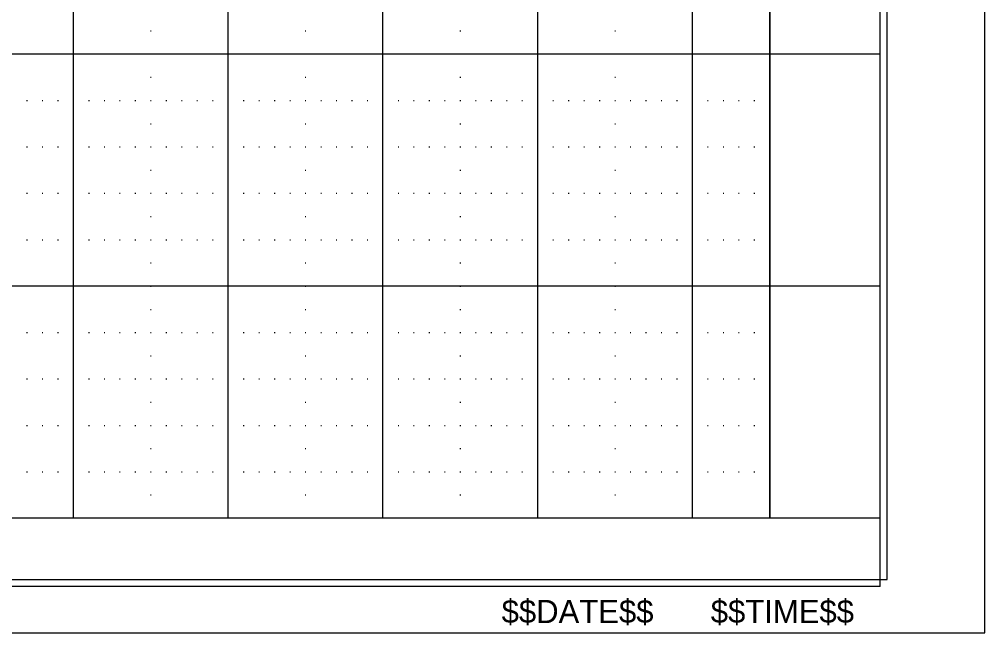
# Model space of a CAD drawing. Extents: x -1.3 to 32, y -0.2 to 20.7.
# Drawn here: x 27.879 to 32.038, y -0.229 to 2.414 of the extents above; entities that cross this region are included whole.
import ezdxf

# ---------------------------------------------------------------- set-up
doc = ezdxf.new("R2010")
doc.units = 0
for name, color, linetype in [('Level 1', 7, 'Continuous'), ('Level 37', 7, 'Continuous'), ('Level 4', 7, 'Continuous'), ('Level 48', 7, 'Continuous'), ('Level 5', 7, 'Continuous'), ('Level 62', 7, 'Continuous'), ('Level 63', 7, 'Continuous')]:
    doc.layers.add(name, color=color, linetype=linetype)

msp = doc.modelspace()

# ---------------------------------------------------------------- linework, layer by layer
at = {"layer": 'Level 1'}
for q in [(31.588, 20.516), (-0.03, -0.03)]:
    msp.add_line((31.588, -0.03), q, dxfattribs=at)
at = {"layer": 'Level 37'}
for p, q in [((31.1123, 10.264), (31.1123, 0.264)), ((31.1123, 0.264), (0.7787, 0.2635))]:
    msp.add_line(p, q, dxfattribs=at)
at = {"layer": 'Level 4'}
for p, q in [((28.1123, 0.264), (28.1123, 10.264)), ((28.779, 0.264), (28.779, 10.264)), ((29.4457, 0.264), (29.4457, 10.264)), ((30.1123, 0.264), (30.1123, 10.264)), ((30.779, 0.264), (30.779, 10.264)), ((31.1123, 0.264), (31.1123, 10.264)), ((31.588, 2.264), (-0.03, 2.264)), ((31.588, 1.264), (-0.03, 1.264)), ((31.588, 0.264), (0.4456, 0.264))]:
    msp.add_line(p, q, dxfattribs=at)
at = {"layer": 'Level 5'}
for p, q in [((28.444, 2.364), (28.4473, 2.364)), ((29.1107, 2.364), (29.114, 2.364)), ((29.7773, 2.364), (29.7807, 2.364)), ((30.444, 2.364), (30.4473, 2.364)), ((28.444, 2.164), (28.4473, 2.164)), ((29.1107, 2.164), (29.114, 2.164)), ((29.7773, 2.164), (29.7807, 2.164)), ((30.444, 2.164), (30.4473, 2.164)), ((27.9107, 2.064), (27.914, 2.064)), ((27.9773, 2.064), (27.9807, 2.064)), ((28.044, 2.064), (28.0473, 2.064)), ((28.1773, 2.064), (28.1807, 2.064)), ((28.244, 2.064), (28.2473, 2.064)), ((28.3107, 2.064), (28.314, 2.064)), ((28.3773, 2.064), (28.3807, 2.064)), ((28.444, 2.064), (28.4473, 2.064)), ((28.5107, 2.064), (28.514, 2.064)), ((28.5773, 2.064), (28.5807, 2.064)), ((28.644, 2.064), (28.6473, 2.064)), ((28.7107, 2.064), (28.714, 2.064)), ((28.844, 2.064), (28.8473, 2.064)), ((28.9107, 2.064), (28.914, 2.064)), ((28.9773, 2.064), (28.9807, 2.064)), ((29.044, 2.064), (29.0473, 2.064)), ((29.1107, 2.064), (29.114, 2.064)), ((29.1773, 2.064), (29.1807, 2.064)), ((29.244, 2.064), (29.2473, 2.064)), ((29.3107, 2.064), (29.314, 2.064)), ((29.3773, 2.064), (29.3807, 2.064)), ((29.5107, 2.064), (29.514, 2.064)), ((29.5773, 2.064), (29.5807, 2.064)), ((29.644, 2.064), (29.6473, 2.064)), ((29.7107, 2.064), (29.714, 2.064)), ((29.7773, 2.064), (29.7807, 2.064)), ((29.844, 2.064), (29.8473, 2.064)), ((29.9107, 2.064), (29.914, 2.064)), ((29.9773, 2.064), (29.9807, 2.064)), ((30.044, 2.064), (30.0473, 2.064)), ((30.1773, 2.064), (30.1807, 2.064)), ((30.244, 2.064), (30.2473, 2.064)), ((30.3107, 2.064), (30.314, 2.064)), ((30.3773, 2.064), (30.3807, 2.064)), ((30.444, 2.064), (30.4473, 2.064)), ((30.5107, 2.064), (30.514, 2.064)), ((30.5773, 2.064), (30.5807, 2.064)), ((30.644, 2.064), (30.6473, 2.064)), ((30.7107, 2.064), (30.714, 2.064)), ((30.844, 2.064), (30.8473, 2.064)), ((30.9107, 2.064), (30.914, 2.064)), ((30.9773, 2.064), (30.9807, 2.064)), ((31.044, 2.064), (31.0473, 2.064)), ((28.444, 1.964), (28.4473, 1.964)), ((29.1107, 1.964), (29.114, 1.964)), ((29.7773, 1.964), (29.7807, 1.964)), ((30.444, 1.964), (30.4473, 1.964)), ((27.9107, 1.864), (27.914, 1.864)), ((27.9773, 1.864), (27.9807, 1.864)), ((28.044, 1.864), (28.0473, 1.864)), ((28.1773, 1.864), (28.1807, 1.864)), ((28.244, 1.864), (28.2473, 1.864)), ((28.3107, 1.864), (28.314, 1.864)), ((28.3773, 1.864), (28.3807, 1.864)), ((28.444, 1.864), (28.4473, 1.864)), ((28.5107, 1.864), (28.514, 1.864)), ((28.5773, 1.864), (28.5807, 1.864)), ((28.644, 1.864), (28.6473, 1.864)), ((28.7107, 1.864), (28.714, 1.864)), ((28.844, 1.864), (28.8473, 1.864)), ((28.9107, 1.864), (28.914, 1.864)), ((28.9773, 1.864), (28.9807, 1.864)), ((29.044, 1.864), (29.0473, 1.864)), ((29.1107, 1.864), (29.114, 1.864)), ((29.1773, 1.864), (29.1807, 1.864)), ((29.244, 1.864), (29.2473, 1.864)), ((29.3107, 1.864), (29.314, 1.864)), ((29.3773, 1.864), (29.3807, 1.864)), ((29.5107, 1.864), (29.514, 1.864)), ((29.5773, 1.864), (29.5807, 1.864)), ((29.644, 1.864), (29.6473, 1.864)), ((29.7107, 1.864), (29.714, 1.864)), ((29.7773, 1.864), (29.7807, 1.864)), ((29.844, 1.864), (29.8473, 1.864)), ((29.9107, 1.864), (29.914, 1.864)), ((29.9773, 1.864), (29.9807, 1.864)), ((30.044, 1.864), (30.0473, 1.864)), ((30.1773, 1.864), (30.1807, 1.864)), ((30.244, 1.864), (30.2473, 1.864)), ((30.3107, 1.864), (30.314, 1.864)), ((30.3773, 1.864), (30.3807, 1.864)), ((30.444, 1.864), (30.4473, 1.864)), ((30.5107, 1.864), (30.514, 1.864)), ((30.5773, 1.864), (30.5807, 1.864)), ((30.644, 1.864), (30.6473, 1.864)), ((30.7107, 1.864), (30.714, 1.864)), ((30.844, 1.864), (30.8473, 1.864)), ((30.9107, 1.864), (30.914, 1.864)), ((30.9773, 1.864), (30.9807, 1.864)), ((31.044, 1.864), (31.0473, 1.864)), ((28.444, 1.764), (28.4473, 1.764)), ((29.1107, 1.764), (29.114, 1.764)), ((29.7773, 1.764), (29.7807, 1.764)), ((30.444, 1.764), (30.4473, 1.764)), ((27.9107, 1.664), (27.914, 1.664)), ((27.9773, 1.664), (27.9807, 1.664)), ((28.044, 1.664), (28.0473, 1.664)), ((28.1773, 1.664), (28.1807, 1.664)), ((28.244, 1.664), (28.2473, 1.664)), ((28.3107, 1.664), (28.314, 1.664)), ((28.3773, 1.664), (28.3807, 1.664)), ((28.444, 1.664), (28.4473, 1.664)), ((28.5107, 1.664), (28.514, 1.664)), ((28.5773, 1.664), (28.5807, 1.664)), ((28.644, 1.664), (28.6473, 1.664)), ((28.7107, 1.664), (28.714, 1.664)), ((28.844, 1.664), (28.8473, 1.664)), ((28.9107, 1.664), (28.914, 1.664)), ((28.9773, 1.664), (28.9807, 1.664)), ((29.044, 1.664), (29.0473, 1.664)), ((29.1107, 1.664), (29.114, 1.664)), ((29.1773, 1.664), (29.1807, 1.664)), ((29.244, 1.664), (29.2473, 1.664)), ((29.3107, 1.664), (29.314, 1.664)), ((29.3773, 1.664), (29.3807, 1.664)), ((29.5107, 1.664), (29.514, 1.664)), ((29.5773, 1.664), (29.5807, 1.664)), ((29.644, 1.664), (29.6473, 1.664)), ((29.7107, 1.664), (29.714, 1.664)), ((29.7773, 1.664), (29.7807, 1.664)), ((29.844, 1.664), (29.8473, 1.664)), ((29.9107, 1.664), (29.914, 1.664)), ((29.9773, 1.664), (29.9807, 1.664)), ((30.044, 1.664), (30.0473, 1.664)), ((30.1773, 1.664), (30.1807, 1.664)), ((30.244, 1.664), (30.2473, 1.664)), ((30.3107, 1.664), (30.314, 1.664)), ((30.3773, 1.664), (30.3807, 1.664)), ((30.444, 1.664), (30.4473, 1.664)), ((30.5107, 1.664), (30.514, 1.664)), ((30.5773, 1.664), (30.5807, 1.664)), ((30.644, 1.664), (30.6473, 1.664)), ((30.7107, 1.664), (30.714, 1.664)), ((30.844, 1.664), (30.8473, 1.664)), ((30.9107, 1.664), (30.914, 1.664)), ((30.9773, 1.664), (30.9807, 1.664)), ((31.044, 1.664), (31.0473, 1.664)), ((28.444, 1.564), (28.4473, 1.564)), ((29.1107, 1.564), (29.114, 1.564)), ((29.7773, 1.564), (29.7807, 1.564)), ((30.444, 1.564), (30.4473, 1.564)), ((27.9107, 1.464), (27.914, 1.464)), ((27.9773, 1.464), (27.9807, 1.464)), ((28.044, 1.464), (28.0473, 1.464)), ((28.1773, 1.464), (28.1807, 1.464)), ((28.244, 1.464), (28.2473, 1.464)), ((28.3107, 1.464), (28.314, 1.464)), ((28.3773, 1.464), (28.3807, 1.464)), ((28.444, 1.464), (28.4473, 1.464)), ((28.5107, 1.464), (28.514, 1.464)), ((28.5773, 1.464), (28.5807, 1.464)), ((28.644, 1.464), (28.6473, 1.464)), ((28.7107, 1.464), (28.714, 1.464)), ((28.844, 1.464), (28.8473, 1.464)), ((28.9107, 1.464), (28.914, 1.464)), ((28.9773, 1.464), (28.9807, 1.464)), ((29.044, 1.464), (29.0473, 1.464)), ((29.1107, 1.464), (29.114, 1.464)), ((29.1773, 1.464), (29.1807, 1.464)), ((29.244, 1.464), (29.2473, 1.464)), ((29.3107, 1.464), (29.314, 1.464)), ((29.3773, 1.464), (29.3807, 1.464)), ((29.5107, 1.464), (29.514, 1.464)), ((29.5773, 1.464), (29.5807, 1.464)), ((29.644, 1.464), (29.6473, 1.464)), ((29.7107, 1.464), (29.714, 1.464)), ((29.7773, 1.464), (29.7807, 1.464)), ((29.844, 1.464), (29.8473, 1.464)), ((29.9107, 1.464), (29.914, 1.464)), ((29.9773, 1.464), (29.9807, 1.464)), ((30.044, 1.464), (30.0473, 1.464)), ((30.1773, 1.464), (30.1807, 1.464)), ((30.244, 1.464), (30.2473, 1.464)), ((30.3107, 1.464), (30.314, 1.464)), ((30.3773, 1.464), (30.3807, 1.464)), ((30.444, 1.464), (30.4473, 1.464)), ((30.5107, 1.464), (30.514, 1.464)), ((30.5773, 1.464), (30.5807, 1.464)), ((30.644, 1.464), (30.6473, 1.464)), ((30.7107, 1.464), (30.714, 1.464)), ((30.844, 1.464), (30.8473, 1.464)), ((30.9107, 1.464), (30.914, 1.464)), ((30.9773, 1.464), (30.9807, 1.464)), ((31.044, 1.464), (31.0473, 1.464)), ((28.444, 1.364), (28.4473, 1.364)), ((29.1107, 1.364), (29.114, 1.364)), ((29.7773, 1.364), (29.7807, 1.364)), ((30.444, 1.364), (30.4473, 1.364)), ((28.444, 1.264), (28.4473, 1.264)), ((29.1107, 1.264), (29.114, 1.264)), ((29.7773, 1.264), (29.7807, 1.264)), ((30.444, 1.264), (30.4473, 1.264)), ((28.444, 1.164), (28.4473, 1.164)), ((29.1107, 1.164), (29.114, 1.164)), ((29.7773, 1.164), (29.7807, 1.164)), ((30.444, 1.164), (30.4473, 1.164)), ((27.9107, 1.064), (27.914, 1.064)), ((27.9773, 1.064), (27.9807, 1.064)), ((28.044, 1.064), (28.0473, 1.064)), ((28.1773, 1.064), (28.1807, 1.064)), ((28.244, 1.064), (28.2473, 1.064)), ((28.3107, 1.064), (28.314, 1.064)), ((28.3773, 1.064), (28.3807, 1.064)), ((28.444, 1.064), (28.4473, 1.064)), ((28.5107, 1.064), (28.514, 1.064)), ((28.5773, 1.064), (28.5807, 1.064)), ((28.644, 1.064), (28.6473, 1.064)), ((28.7107, 1.064), (28.714, 1.064)), ((28.844, 1.064), (28.8473, 1.064)), ((28.9107, 1.064), (28.914, 1.064)), ((28.9773, 1.064), (28.9807, 1.064)), ((29.044, 1.064), (29.0473, 1.064)), ((29.1107, 1.064), (29.114, 1.064)), ((29.1773, 1.064), (29.1807, 1.064)), ((29.244, 1.064), (29.2473, 1.064)), ((29.3107, 1.064), (29.314, 1.064)), ((29.3773, 1.064), (29.3807, 1.064)), ((29.5107, 1.064), (29.514, 1.064)), ((29.5773, 1.064), (29.5807, 1.064)), ((29.644, 1.064), (29.6473, 1.064)), ((29.7107, 1.064), (29.714, 1.064)), ((29.7773, 1.064), (29.7807, 1.064)), ((29.844, 1.064), (29.8473, 1.064)), ((29.9107, 1.064), (29.914, 1.064)), ((29.9773, 1.064), (29.9807, 1.064)), ((30.044, 1.064), (30.0473, 1.064)), ((30.1773, 1.064), (30.1807, 1.064)), ((30.244, 1.064), (30.2473, 1.064)), ((30.3107, 1.064), (30.314, 1.064)), ((30.3773, 1.064), (30.3807, 1.064)), ((30.444, 1.064), (30.4473, 1.064)), ((30.5107, 1.064), (30.514, 1.064)), ((30.5773, 1.064), (30.5807, 1.064)), ((30.644, 1.064), (30.6473, 1.064)), ((30.7107, 1.064), (30.714, 1.064)), ((30.844, 1.064), (30.8473, 1.064)), ((30.9107, 1.064), (30.914, 1.064)), ((30.9773, 1.064), (30.9807, 1.064)), ((31.044, 1.064), (31.0473, 1.064)), ((28.444, 0.964), (28.4473, 0.964)), ((29.1107, 0.964), (29.114, 0.964)), ((29.7773, 0.964), (29.7807, 0.964)), ((30.444, 0.964), (30.4473, 0.964)), ((27.9107, 0.864), (27.914, 0.864)), ((27.9773, 0.864), (27.9807, 0.864)), ((28.044, 0.864), (28.0473, 0.864)), ((28.1773, 0.864), (28.1807, 0.864)), ((28.244, 0.864), (28.2473, 0.864)), ((28.3107, 0.864), (28.314, 0.864)), ((28.3773, 0.864), (28.3807, 0.864)), ((28.444, 0.864), (28.4473, 0.864)), ((28.5107, 0.864), (28.514, 0.864)), ((28.5773, 0.864), (28.5807, 0.864)), ((28.644, 0.864), (28.6473, 0.864)), ((28.7107, 0.864), (28.714, 0.864)), ((28.844, 0.864), (28.8473, 0.864)), ((28.9107, 0.864), (28.914, 0.864)), ((28.9773, 0.864), (28.9807, 0.864)), ((29.044, 0.864), (29.0473, 0.864)), ((29.1107, 0.864), (29.114, 0.864)), ((29.1773, 0.864), (29.1807, 0.864)), ((29.244, 0.864), (29.2473, 0.864)), ((29.3107, 0.864), (29.314, 0.864)), ((29.3773, 0.864), (29.3807, 0.864)), ((29.5107, 0.864), (29.514, 0.864)), ((29.5773, 0.864), (29.5807, 0.864)), ((29.644, 0.864), (29.6473, 0.864)), ((29.7107, 0.864), (29.714, 0.864)), ((29.7773, 0.864), (29.7807, 0.864)), ((29.844, 0.864), (29.8473, 0.864)), ((29.9107, 0.864), (29.914, 0.864)), ((29.9773, 0.864), (29.9807, 0.864)), ((30.044, 0.864), (30.0473, 0.864)), ((30.1773, 0.864), (30.1807, 0.864)), ((30.244, 0.864), (30.2473, 0.864)), ((30.3107, 0.864), (30.314, 0.864)), ((30.3773, 0.864), (30.3807, 0.864)), ((30.444, 0.864), (30.4473, 0.864)), ((30.5107, 0.864), (30.514, 0.864)), ((30.5773, 0.864), (30.5807, 0.864)), ((30.644, 0.864), (30.6473, 0.864)), ((30.7107, 0.864), (30.714, 0.864)), ((30.844, 0.864), (30.8473, 0.864)), ((30.9107, 0.864), (30.914, 0.864)), ((30.9773, 0.864), (30.9807, 0.864)), ((31.044, 0.864), (31.0473, 0.864)), ((28.444, 0.764), (28.4473, 0.764)), ((29.1107, 0.764), (29.114, 0.764)), ((29.7773, 0.764), (29.7807, 0.764)), ((30.444, 0.764), (30.4473, 0.764)), ((27.9107, 0.664), (27.914, 0.664)), ((27.9773, 0.664), (27.9807, 0.664)), ((28.044, 0.664), (28.0473, 0.664)), ((28.1773, 0.664), (28.1807, 0.664)), ((28.244, 0.664), (28.2473, 0.664)), ((28.3107, 0.664), (28.314, 0.664)), ((28.3773, 0.664), (28.3807, 0.664)), ((28.444, 0.664), (28.4473, 0.664)), ((28.5107, 0.664), (28.514, 0.664)), ((28.5773, 0.664), (28.5807, 0.664)), ((28.644, 0.664), (28.6473, 0.664)), ((28.7107, 0.664), (28.714, 0.664)), ((28.844, 0.664), (28.8473, 0.664)), ((28.9107, 0.664), (28.914, 0.664)), ((28.9773, 0.664), (28.9807, 0.664)), ((29.044, 0.664), (29.0473, 0.664)), ((29.1107, 0.664), (29.114, 0.664)), ((29.1773, 0.664), (29.1807, 0.664)), ((29.244, 0.664), (29.2473, 0.664)), ((29.3107, 0.664), (29.314, 0.664)), ((29.3773, 0.664), (29.3807, 0.664)), ((29.5107, 0.664), (29.514, 0.664)), ((29.5773, 0.664), (29.5807, 0.664)), ((29.644, 0.664), (29.6473, 0.664)), ((29.7107, 0.664), (29.714, 0.664)), ((29.7773, 0.664), (29.7807, 0.664)), ((29.844, 0.664), (29.8473, 0.664)), ((29.9107, 0.664), (29.914, 0.664)), ((29.9773, 0.664), (29.9807, 0.664)), ((30.044, 0.664), (30.0473, 0.664)), ((30.1773, 0.664), (30.1807, 0.664)), ((30.244, 0.664), (30.2473, 0.664)), ((30.3107, 0.664), (30.314, 0.664)), ((30.3773, 0.664), (30.3807, 0.664)), ((30.444, 0.664), (30.4473, 0.664)), ((30.5107, 0.664), (30.514, 0.664)), ((30.5773, 0.664), (30.5807, 0.664)), ((30.644, 0.664), (30.6473, 0.664)), ((30.7107, 0.664), (30.714, 0.664)), ((30.844, 0.664), (30.8473, 0.664)), ((30.9107, 0.664), (30.914, 0.664)), ((30.9773, 0.664), (30.9807, 0.664)), ((31.044, 0.664), (31.0473, 0.664)), ((28.444, 0.564), (28.4473, 0.564)), ((29.1107, 0.564), (29.114, 0.564)), ((29.7773, 0.564), (29.7807, 0.564)), ((30.444, 0.564), (30.4473, 0.564)), ((27.9107, 0.464), (27.914, 0.464)), ((27.9773, 0.464), (27.9807, 0.464)), ((28.044, 0.464), (28.0473, 0.464)), ((28.1773, 0.464), (28.1807, 0.464)), ((28.244, 0.464), (28.2473, 0.464)), ((28.3107, 0.464), (28.314, 0.464)), ((28.3773, 0.464), (28.3807, 0.464)), ((28.444, 0.464), (28.4473, 0.464)), ((28.5107, 0.464), (28.514, 0.464)), ((28.5773, 0.464), (28.5807, 0.464)), ((28.644, 0.464), (28.6473, 0.464)), ((28.7107, 0.464), (28.714, 0.464)), ((28.844, 0.464), (28.8473, 0.464)), ((28.9107, 0.464), (28.914, 0.464)), ((28.9773, 0.464), (28.9807, 0.464)), ((29.044, 0.464), (29.0473, 0.464)), ((29.1107, 0.464), (29.114, 0.464)), ((29.1773, 0.464), (29.1807, 0.464)), ((29.244, 0.464), (29.2473, 0.464)), ((29.3107, 0.464), (29.314, 0.464)), ((29.3773, 0.464), (29.3807, 0.464)), ((29.5107, 0.464), (29.514, 0.464)), ((29.5773, 0.464), (29.5807, 0.464)), ((29.644, 0.464), (29.6473, 0.464)), ((29.7107, 0.464), (29.714, 0.464)), ((29.7773, 0.464), (29.7807, 0.464)), ((29.844, 0.464), (29.8473, 0.464)), ((29.9107, 0.464), (29.914, 0.464)), ((29.9773, 0.464), (29.9807, 0.464)), ((30.044, 0.464), (30.0473, 0.464)), ((30.1773, 0.464), (30.1807, 0.464)), ((30.244, 0.464), (30.2473, 0.464)), ((30.3107, 0.464), (30.314, 0.464)), ((30.3773, 0.464), (30.3807, 0.464)), ((30.444, 0.464), (30.4473, 0.464)), ((30.5107, 0.464), (30.514, 0.464)), ((30.5773, 0.464), (30.5807, 0.464)), ((30.644, 0.464), (30.6473, 0.464)), ((30.7107, 0.464), (30.714, 0.464)), ((30.844, 0.464), (30.8473, 0.464)), ((30.9107, 0.464), (30.914, 0.464)), ((30.9773, 0.464), (30.9807, 0.464)), ((31.044, 0.464), (31.0473, 0.464)), ((28.444, 0.364), (28.4473, 0.364)), ((29.1107, 0.364), (29.114, 0.364)), ((29.7773, 0.364), (29.7807, 0.364)), ((30.444, 0.364), (30.4473, 0.364))]:
    msp.add_line(p, q, dxfattribs=at)
at = {"layer": 'Level 62'}
for p, q in [((31.618, 0), (31.618, 10.294)), ((2.4642, 0), (31.618, 0))]:
    msp.add_line(p, q, dxfattribs=at)
at = {"layer": 'Level 63'}
msp.add_lwpolyline([(-1.292, -0.2295), (32.038, -0.2295), (32.038, 20.7175), (-1.292, 20.7175)], close=True, dxfattribs=at)

# ---------------------------------------------------------------- texts
at = {"layer": 'Level 48'}
for s, p in [('$$DATE$$', (29.957, -0.188)), ('$$TIME$$', (30.858, -0.188))]:
    msp.add_text(s, height=0.1, dxfattribs=at).set_placement(p)

doc.saveas('drawing.dxf')
